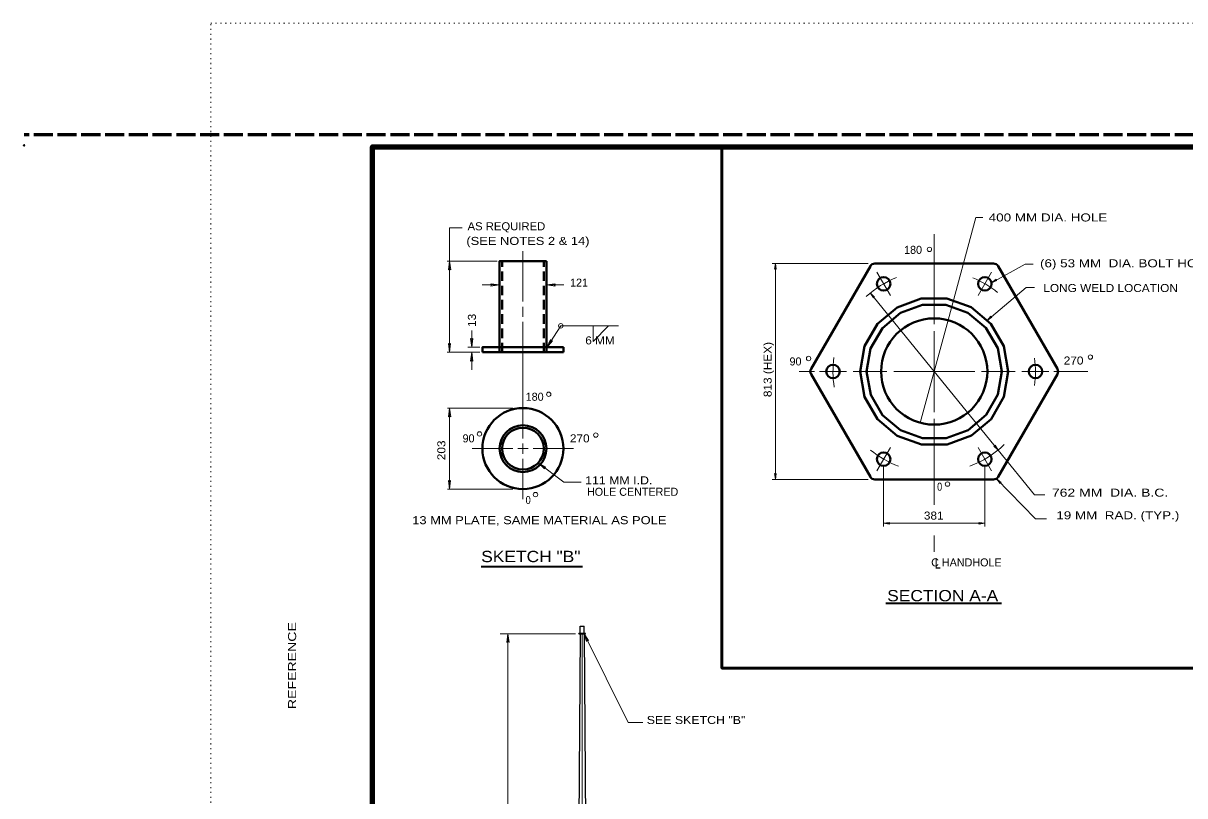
# Model space of a CAD drawing. Extents: x 312583 to 312854, y 144419 to 144597.
# Drawn here: x 312583.5 to 312693.4, y 144523.7 to 144596.8 of the extents above; entities that cross this region are included whole.
import ezdxf
from ezdxf.enums import TextEntityAlignment as Align

# ---------------------------------------------------------------- set-up
doc = ezdxf.new("R2010")
doc.units = 0
doc.header["$LTSCALE"] = 0.3
doc.header["$PDMODE"] = 32
doc.header["$PDSIZE"] = 0.15
for name, pattern in [('DOTTED', [1.5, 0.3, -1.2]), ('LONG_DASHED', [7.5, 6, -1.5]), ('MEDIUM_DASHED', [4.5, 3, -1.5])]:
    doc.linetypes.add(name, pattern=pattern)
for name, color, linetype, lineweight in [('1', 7, 'Continuous', 13), ('2', 7, 'Continuous', 13), ('61', 7, 'LONG_DASHED', 60), ('63', 7, 'DOTTED', 13)]:
    doc.layers.add(name, color=color, linetype=linetype, lineweight=lineweight)

msp = doc.modelspace()

# ---------------------------------------------------------------- linework, layer by layer
at = {"layer": '1'}
for p, q in [((312623.8056, 144577.4285), (312623.8056, 144565.6371)), ((312624.9862, 144577.4285), (312623.8056, 144577.4285)), ((312630.7516, 144570.4288), (312630.7516, 144575.2205)), ((312628.2982, 144574.2621), (312623.5679, 144574.2621)), ((312626.8799, 144572.0081), (312628.5359, 144572.0081)), ((312634.6232, 144572.0081), (312632.9672, 144572.0081)), ((312630.7516, 144568.9951), (312630.7516, 144569.9535)), ((312630.7516, 144557.4798), (312630.7516, 144568.5121)), ((312625.9062, 144567.6849), (312625.9062, 144566.1201)), ((312626.6806, 144566.1201), (312625.5306, 144566.1201)), ((312626.6806, 144565.6371), (312623.5679, 144565.6371)), ((312625.9062, 144563.9811), (312625.9062, 144565.6371)), ((312629.7932, 144560.3548), (312623.6062, 144560.3548)), ((312623.8056, 144560.3548), (312623.8056, 144552.6881)), ((312629.7932, 144556.5215), (312625.9599, 144556.5215)), ((312630.7516, 144556.5215), (312630.7516, 144556.9968)), ((312630.7516, 144556.5215), (312631.2346, 144556.5215)), ((312631.7099, 144556.5215), (312635.5432, 144556.5215)), ((312679.2716, 144549.8852), (312675.5916, 144553.6572)), ((312629.7932, 144552.6881), (312623.6062, 144552.6881)), ((312636.3575, 144539.0263), (312636.3575, 144439.0913)), ((312636.5414, 144538.9802), (312640.7044, 144530.6009)), ((312640.7044, 144530.6009), (312642.1074, 144530.6009))]:
    msp.add_line(p, q, dxfattribs=at)
at = {"layer": '1', "linetype": 'MEDIUM_DASHED', "lineweight": 40}
for p, q in [((312628.7736, 144565.6371), (312628.7736, 144574.2621)), ((312632.7296, 144565.6371), (312632.7296, 144574.2621))]:
    msp.add_line(p, q, dxfattribs=at)
at = {"layer": '1', "lineweight": 40}
for p, q in [((312632.9672, 144565.6371), (312632.9672, 144574.2621)), ((312634.5849, 144565.6371), (312634.5849, 144566.1201)), ((312626.9182, 144565.6371), (312634.5849, 144565.6371))]:
    msp.add_line(p, q, dxfattribs=at)
at = {"layer": '1', "lineweight": 35}
for p, q in [((312626.7934, 144545.3599), (312636.3921, 144545.3599)), ((312665.1077, 144541.8799), (312676.0375, 144541.8799))]:
    msp.add_line(p, q, dxfattribs=at)
at = {"layer": '1', "lineweight": 25}
for p, q in [((312636.1734, 144539.7009), (312636.5414, 144539.7009)), ((312636.1734, 144539.0186), (312636.1734, 144539.7009)), ((312636.5414, 144539.0186), (312636.5414, 144539.7009)), ((312636.0354, 144538.9802), (312636.0354, 144539.0186))]:
    msp.add_line(p, q, dxfattribs=at)
at = {"layer": '1', "lineweight": 158}
msp.add_lwpolyline([(312616.5, 144423.1446), (312616.5, 144585.0846), (312849, 144585.0846)], dxfattribs=at)
at = {"layer": '1', "lineweight": 53}
msp.add_lwpolyline([(312649.5924, 144585.0846), (312649.5924, 144535.7373), (312696.6894, 144535.7373), (312696.6894, 144491.5236), (312798.3536, 144491.5236)], dxfattribs=at)
at = {"layer": '1'}
for points in [[(312623.6982, 144573.4341), (312623.8056, 144574.2621), (312623.9206, 144573.4341), (312623.8056, 144573.5185)], [(312654.725, 144573.4897), (312654.656, 144574.0417), (312654.5793, 144573.4897), (312654.656, 144573.5434)], [(312675.6222, 144572.4329), (312675.1009, 144572.2259), (312675.5532, 144572.5556), (312675.5379, 144572.4636)], [(312627.7079, 144572.1078), (312628.5359, 144572.0081), (312627.7079, 144571.8931), (312627.7846, 144572.0081)], [(312633.7952, 144571.9008), (312632.9672, 144572.0081), (312633.7952, 144572.1231), (312633.7186, 144572.0081)], [(312663.9306, 144570.7769), (312663.6316, 144571.2522), (312664.0379, 144570.8689), (312663.9459, 144570.8612)], [(312675.1392, 144568.9522), (312674.6792, 144568.6456), (312675.0472, 144569.0596), (312675.0549, 144568.9676)], [(312623.9052, 144566.4651), (312623.8056, 144565.6371), (312623.6906, 144566.4651), (312623.8056, 144566.3885)], [(312626.0059, 144566.9481), (312625.9062, 144566.1201), (312625.7912, 144566.9481), (312625.9062, 144566.8638)], [(312633.5422, 144566.7258), (312633.0132, 144566.0818), (312633.3582, 144566.8408), (312633.4119, 144566.7105)], [(312625.7989, 144564.8091), (312625.9062, 144565.6371), (312626.0212, 144564.8091), (312625.9062, 144564.8935)], [(312623.6982, 144559.5268), (312623.8056, 144560.3548), (312623.9206, 144559.5268), (312623.8056, 144559.6035)], [(312675.4382, 144556.8542), (312675.7296, 144556.3866), (312675.3232, 144556.7622), (312675.4152, 144556.7699)], [(312632.7986, 144554.5895), (312632.1929, 144555.1721), (312632.9289, 144554.7658), (312632.7909, 144554.7198)], [(312654.7229, 144554.1479), (312654.6539, 144553.5959), (312654.5772, 144554.1479), (312654.6539, 144554.0942)], [(312623.9052, 144553.5161), (312623.8056, 144552.6881), (312623.6906, 144553.5161), (312623.8056, 144553.4318)], [(312675.9212, 144553.2126), (312675.5916, 144553.6572), (312676.0286, 144553.3122), (312675.9366, 144553.2969)], [(312665.4409, 144549.3792), (312664.8889, 144549.4482), (312665.4409, 144549.5249), (312665.3872, 144549.4482)], [(312673.9202, 144549.5172), (312674.4722, 144549.4482), (312673.9202, 144549.3716), (312673.9739, 144549.4482)]]:
    msp.add_lwpolyline(points, close=True, dxfattribs=at)
at = {"layer": '1', "lineweight": 40}
for points in [[(312628.5359, 144565.6371), (312628.5359, 144574.2621), (312632.9672, 144574.2621)], [(312626.9182, 144565.6371), (312626.9182, 144566.1201), (312634.5849, 144566.1201)]]:
    msp.add_lwpolyline(points, dxfattribs=at)
at = {"layer": '1'}
for points in [[(312633.0132, 144566.0818), (312634.3319, 144568.1441), (312639.7829, 144568.1441)], [(312637.3909, 144568.1058), (312637.3909, 144566.6721), (312638.8629, 144568.1441)], [(312630.7516, 144556.5215), (312630.2762, 144556.5215), (312630.7516, 144556.5215)], [(312630.7516, 144556.5215), (312630.7516, 144556.0385), (312630.7516, 144556.5215)], [(312630.7516, 144555.5631), (312630.7516, 144551.7298), (312630.7516, 144551.7375)], [(312636.2486, 144553.3398), (312634.6309, 144553.3398), (312632.1929, 144555.1721)]]:
    msp.add_lwpolyline(points, dxfattribs=at)
at = {"layer": '1', "lineweight": 25}
msp.add_lwpolyline([(312636.0354, 144538.9802), (312636.6718, 144538.9802), (312636.6718, 144539.0186), (312636.0354, 144539.0186)], dxfattribs=at)
at = {"layer": '1'}
for centre, radius in [((312669.2333, 144575.375), 0.2074), ((312634.3357, 144568.1451), 0.2145), ((312657.7953, 144565.0486), 0.2074), ((312684.4619, 144565.1873), 0.2074), ((312633.1944, 144561.6668), 0.208), ((312626.6413, 144557.911), 0.208), ((312637.6497, 144557.8008), 0.208), ((312670.9405, 144553.1576), 0.2074), ((312631.9428, 144552.1678), 0.208)]:
    msp.add_circle(centre, radius, dxfattribs=at)
at = {"layer": '1', "lineweight": 40}
for radius in [3.8333, 2.2161, 1.9766]:
    msp.add_circle((312630.7525, 144556.5196), radius, dxfattribs=at)
at = {"layer": '1'}
msp.add_point((312583.526, 144585.2246), dxfattribs=at)
at = {"layer": '2'}
for p, q in [((312670.9992, 144568.6762), (312673.6366, 144578.3822)), ((312673.6366, 144578.3822), (312674.2791, 144578.3822)), ((312669.6806, 144568.2929), (312669.6806, 144576.8259)), ((312663.419, 144574.0417), (312654.334, 144574.0417)), ((312654.656, 144553.5947), (312654.656, 144574.0417)), ((312675.1009, 144572.2259), (312678.3056, 144573.9662)), ((312678.3056, 144573.9662), (312679.0433, 144573.9662)), ((312665.5329, 144571.0146), (312664.2526, 144573.2226)), ((312673.8359, 144571.0146), (312675.1162, 144573.2226)), ((312674.6792, 144568.6456), (312678.3976, 144571.7812)), ((312678.3976, 144571.7812), (312679.1835, 144571.7812)), ((312663.6316, 144571.2522), (312675.7296, 144556.3866)), ((312668.3623, 144558.9638), (312670.9992, 144568.6762)), ((312669.6806, 144563.8156), (312669.6806, 144567.6489)), ((312658.3416, 144563.8156), (312656.9079, 144563.8156)), ((312661.3776, 144563.8156), (312658.8246, 144563.8156)), ((312665.2109, 144563.8156), (312662.0139, 144563.8156)), ((312669.6806, 144563.8156), (312665.8472, 144563.8156)), ((312669.6806, 144563.8156), (312669.6806, 144559.9822)), ((312669.6806, 144563.8156), (312673.5139, 144563.8156)), ((312674.1579, 144563.8156), (312677.3472, 144563.8156)), ((312677.9912, 144563.8156), (312680.5442, 144563.8156)), ((312681.0196, 144563.8156), (312684.2319, 144563.8156)), ((312669.6806, 144559.3459), (312669.6806, 144551.1955)), ((312665.5329, 144556.6242), (312664.2526, 144554.4162)), ((312673.8359, 144556.6242), (312675.1162, 144554.4162)), ((312664.8889, 144554.8839), (312664.8889, 144549.1339)), ((312674.4722, 144554.8839), (312674.4722, 144549.1339)), ((312663.419, 144553.5947), (312654.334, 144553.5947)), ((312674.4722, 144549.4482), (312664.8889, 144549.4482)), ((312679.2716, 144549.8852), (312680.3053, 144549.8852)), ((312669.6806, 144546.7496), (312669.6806, 144548.3059)), ((312635.7288, 144538.9802), (312628.5988, 144538.9802)), ((312629.3348, 144538.9802), (312629.2351, 144538.1676)), ((312629.2351, 144538.1676), (312629.3348, 144538.4282)), ((312629.3348, 144443.1469), (312629.3348, 144538.9802)), ((312629.3348, 144538.9802), (312629.4344, 144538.1676)), ((312629.4344, 144538.1676), (312629.3348, 144538.4282))]:
    msp.add_line(p, q, dxfattribs=at)
at = {"layer": '2', "lineweight": 40}
for p, q in [((312658.0195, 144564.0572), (312663.6468, 144573.8015)), ((312675.3079, 144574.0429), (312664.0532, 144574.0429)), ((312681.3492, 144564.0609), (312675.7219, 144573.7976)), ((312658.0196, 144563.5779), (312663.6392, 144553.8336)), ((312675.7204, 144553.835), (312681.3477, 144563.5793)), ((312664.0532, 144553.5965), (312675.3079, 144553.5965))]:
    msp.add_line(p, q, dxfattribs=at)
at = {"layer": '2', "lineweight": 25}
for p, q in [((312636.1734, 144538.9802), (312635.4758, 144443.2696)), ((312636.5414, 144538.9802), (312637.2314, 144443.2696))]:
    msp.add_line(p, q, dxfattribs=at)
at = {"layer": '2', "lineweight": 40}
for points in [[(312668.4769, 144556.9079), (312670.9072, 144556.9156), (312673.1996, 144557.7512), (312675.0626, 144559.3152), (312676.2739, 144561.4312), (312676.6956, 144563.8309), (312676.2662, 144566.2229), (312675.0472, 144568.3312), (312673.1842, 144569.8952), (312670.8919, 144570.7309), (312668.4539, 144570.7232), (312666.1692, 144569.8876), (312664.3062, 144568.3159), (312663.0872, 144566.2076), (312662.6656, 144563.8079), (312663.0949, 144561.4082), (312664.3139, 144559.2999), (312666.1846, 144557.7359)], [(312668.5766, 144557.5136), (312670.7999, 144557.5136), (312672.8929, 144558.2802), (312674.5949, 144559.7062), (312675.7066, 144561.6382), (312676.0899, 144563.8309), (312675.6989, 144566.0159), (312674.5796, 144567.9402), (312672.8776, 144569.3662), (312670.7846, 144570.1252), (312668.5612, 144570.1252), (312666.4759, 144569.3586), (312664.7739, 144567.9249), (312663.6622, 144566.0006), (312663.2789, 144563.8079), (312663.6699, 144561.6229), (312664.7816, 144559.6986), (312666.4912, 144558.2649)]]:
    msp.add_lwpolyline(points, close=True, dxfattribs=at)
at = {"layer": '2'}
msp.add_lwpolyline([(312675.7296, 144556.3866), (312679.1719, 144552.1546), (312680.1651, 144552.1546)], dxfattribs=at)
msp.add_lwpolyline([(312636.9478, 144538.3592), (312636.5414, 144538.9802), (312636.7791, 144538.2749), (312636.8328, 144538.3822)], close=True, dxfattribs=at)
at = {"layer": '2', "lineweight": 40}
for centre, radius in [((312664.8908, 144572.1179), 0.6389), ((312674.4742, 144572.1179), 0.6389), ((312669.6825, 144563.8188), 5.0312), ((312660.0992, 144563.8188), 0.6389), ((312679.2658, 144563.8188), 0.6389), ((312664.8908, 144555.5196), 0.6389), ((312674.4742, 144555.5196), 0.6389)]:
    msp.add_circle(centre, radius, dxfattribs=at)
for centre, start, end in [((312664.0571, 144573.5618), 90, 150.01281), ((312675.3081, 144573.5618), 30.03617, 90), ((312658.4345, 144563.8176), 149.99102, 210.01335), ((312680.9327, 144563.8188), 330.0042, 29.98677), ((312664.0572, 144554.0757), 209.97631, 270), ((312675.3079, 144554.0757), 270, 329.98986)]:
    msp.add_arc(centre, 0.4792, start, end, dxfattribs=at)
at = {"layer": '2'}
for start, end in [(111.87909, 132.13678), (51.23069, 67.66913), (172.10692, 188.98978), (351.97155, 7.54179), (231.00503, 249.344), (290.62798, 313.81704)]:
    msp.add_arc((312669.6825, 144563.8188), 9.5833, start, end, dxfattribs=at)
msp.add_point((312657.9527, 144563.8144), dxfattribs=at)
at = {"layer": '61'}
msp.add_line((312851.75, 144586.2246), (312583.526, 144586.2246), dxfattribs=at)
at = {"layer": '63'}
for p, q in [((312601.2, 144596.7846), (312853.5, 144596.7846)), ((312601.2, 144418.5846), (312601.2, 144596.7846))]:
    msp.add_line(p, q, dxfattribs=at)

# ---------------------------------------------------------------- texts
at = {"layer": '1'}
for s, height, width, p in [('400 MM DIA. HOLE', 0.76, 1.25, (312674.8411, 144578.0201)), ('AS REQUIRED', 0.76, 1.05, (312625.5108, 144577.1853)), ('(SEE NOTES 2 & 14)', 0.76, 1.2, (312625.3947, 144575.7988)), ('(6) 53 MM  DIA. BOLT HOLES', 0.76, 1.25, (312679.6962, 144573.6809)), ('LONG WELD LOCATION', 0.76, 1.1, (312680.0127, 144571.3401)), ('6 MM', 0.76, 1.1, (312636.6514, 144566.3818)), ('270', 0.76, 1.1, (312681.9438, 144564.4766)), ('270', 0.76, 1.1, (312635.197, 144557.1098)), ('111 MM I.D.', 0.76, 1.15, (312636.6396, 144553.1373)), ('0', 0.76, 0.85, (312669.9556, 144552.5319)), ('762 MM  DIA. B.C.', 0.76, 1.3, (312680.8229, 144551.9713)), ('0', 0.76, 0.85, (312631.0089, 144551.272)), ('381 ', 0.76, 1.1, (312668.7034, 144549.8006)), ('19 MM  RAD. (TYP.)', 0.76, 1.25, (312681.2391, 144549.8257)), ('13 MM PLATE, SAME MATERIAL AS POLE', 0.76, 1.2, (312620.2746, 144549.3646)), ('L', 0.9966, 0.75, (312669.7419, 144545.1549))]:
    msp.add_text(s, height=height, dxfattribs=dict(at, width=width)).set_placement(p)
for s, p in [('180', (312666.832, 144574.954)), ('121 ', (312635.2136, 144571.8516)), ('90', (312655.9879, 144564.3924)), ('180', (312631.0135, 144561.0484)), ('90', (312625.0399, 144557.1098)), ('HOLE CENTERED', (312636.8148, 144552.0533)), ('C HANDHOLE', (312669.3969, 144545.3688))]:
    msp.add_text(s, height=0.76, dxfattribs=at).set_placement(p)
for s, height, width, p in [('13 ', 0.76, 1.1, (312626.3009, 144568.0362)), ('813 (HEX)', 0.76, 1.1, (312654.2927, 144561.3942)), ('203', 0.76, 1.1, (312623.4089, 144555.4205)), ('REFERENCE                                                              ', 0.7682, 1.3, (312609.2854, 144531.8549))]:
    msp.add_text(s, height=height, rotation=90, dxfattribs=dict(at, width=width)).set_placement(p)
at = {"layer": '1', "width": 1.15}
for s, p in [('SKETCH "B"', (312631.4975, 144545.7733)), ('SECTION A-A', (312670.4848, 144542.0648))]:
    msp.add_text(s, height=1.07, dxfattribs=at).set_placement(p, align=Align.CENTER)
at = {"layer": '2', "width": 1.15}
msp.add_text('SEE SKETCH "B"', height=0.76, dxfattribs=at).set_placement((312642.4698, 144530.4515))

doc.saveas('drawing.dxf')
